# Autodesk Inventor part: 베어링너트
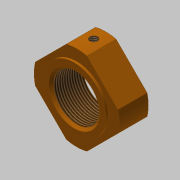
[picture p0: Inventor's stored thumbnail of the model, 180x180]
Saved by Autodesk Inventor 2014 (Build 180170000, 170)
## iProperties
Created: 2019-05
Part Number: 베어링너트
Material: 스테인리스강
Document SubType Name: Modeling
Designer: mduedu
Density: 1 g/cm^3
Appearance: 주황색
Author: mduedu
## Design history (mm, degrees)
sketch "스케치1"
  geometry: C1 r 17.5 at (0, 0); 1 further point
  constraints: 1 centre point, 1 coincident
  dimensions: "d0" = 35 diameter of C1
extrude "돌출1" new body sketch "스케치1" distance "d1" = 12; taper "d2" = 0 deg
sketch "스케치2"
  geometry: L1 (-21.213, 0)-(0, 21.213); L2 (0, 21.213)-(21.213, 0); L3 (21.213, 0)-(0, -21.213); L4 (0, -21.213)-(-21.213, 0); L5 (-21.213, 0)-(21.213, 0); L6 (0, 21.213)-(0, -21.213); 1 further point
  constraints: 12 end point, 2 midpoint, 2 parallel, 1 perpendicular, 1 vertical
  dimensions: "d3" = 30 distance of L1.end L2.end; "d5" = 30 distance of L2.end L3.end
extrude "돌출2" sketch "스케치2" stored distance "d6" = 12; taper "d7" = 0 deg
sketch "스케치3"
  geometry: C1 r 13 at (0, 0); 1 further point
  constraints: 1 centre point, 1 coincident
  dimensions: "d8" = 26 diameter of C1
extrude "돌출3" join sketch "스케치3" distance "d9" = 1; taper "d10" = 0 deg
hole "구멍1" diameter "d13" = 18.917; stored, may be unused: countersink angle "d17" = 90 deg, drill point angle "d19" = 118 deg; dims "d11" = 10, "d12" = 10, "d14" = 6, "d15" = 4, "d16" = 2, "d18" = 8
chamfer "모따기1" distance "d20" = 1; stored, may be unused: second distance "d21" = 2, angle "d22" = 45 deg
node "작업 평면1"
sketch "스케치5"
  geometry: L1 (-4.233, 0)-(4.233, 0) reference; 3 further points
  constraints: 1 midpoint, 1 vertical alignment
  dimensions: "d31" = 5 distance from line of point (0, 5) L1
hole "구멍3" sketch "스케치5" at (0, 5) diameter "d32" = 3.242; stored, may be unused: countersink angle "d36" = 90 deg, drill point angle "d38" = 118 deg; dims "d33" = 6, "d34" = 4, "d35" = 2, "d37" = 8
node "솔리드1"
